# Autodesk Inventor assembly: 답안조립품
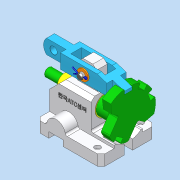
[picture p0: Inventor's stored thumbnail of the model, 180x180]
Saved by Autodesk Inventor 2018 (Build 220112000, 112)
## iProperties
Created: 2022-08
Part Number: 답안조립품
Material: 일반
Document SubType Name: Assembly
Designer: 강의실04
Author: 강의실04
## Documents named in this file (8)
- C:\Users\kimgi\Desktop\720806V1018\답안조립품.iam
- C:\Users\kimgi\Desktop\720806V1018\본체.ipt
- C:\Users\kimgi\Desktop\720806V1018\부시.ipt
- C:\Users\kimgi\Desktop\720806V1018\분할축.ipt
- C:\Users\kimgi\Desktop\720806V1018\분할대.ipt
- C:\Users\kimgi\Desktop\720806V1018\클레비스핀.ipt
- C:\Users\kimgi\Desktop\720806V1018\와셔.ipt
- C:\Users\kimgi\Desktop\720806V1018\분할핀.ipt
